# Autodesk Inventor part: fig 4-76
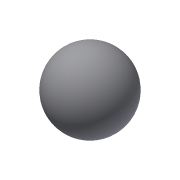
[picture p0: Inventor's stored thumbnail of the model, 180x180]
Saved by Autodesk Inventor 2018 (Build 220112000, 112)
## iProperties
Created: 2012-07
Part Number: fig 4-76
Material: Generic
Document SubType Name: Modeling
Designer: CADCIM
Density: 1 g/cm^3
Appearance: Default
Author: CADCIM
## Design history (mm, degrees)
sketch "Sketch1"
  geometry: L1 (7.807, -5.174)-(-7.807, 5.174); A1 r 9.366 centre (0, 0) between (7.807, -5.174) and (-7.807, 5.174)
  constraints: 2 end point, 2 point on circle, 1 centre point, 1 midpoint
  dimensions: "d0" = 90 deg dimension on A1.centre A1 L1.start L1.end L1
revolve "Revolution1" sketch "Sketch1" stored, may be unused: angle "d0" = 90 deg
body "Solid1"
